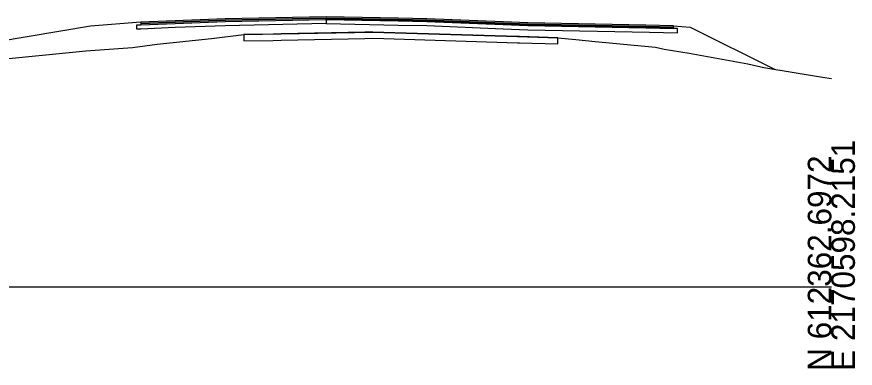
# Model space of a CAD drawing. Extents: x -26 to 1303, y -3010 to 12038.
# Drawn here: x 203.1 to 302.8, y 9990.3 to 10032.1 of the extents above; entities that cross this region are included whole.
import ezdxf

# ---------------------------------------------------------------- set-up
doc = ezdxf.new("R2010")
doc.units = 0
for name, color, linetype in [('RD_GPK_XS_Cell', 7, 'Continuous'), ('RD_XS_Base', 7, 'Continuous'), ('RD_XS_ExGround', 7, 'Continuous'), ('RD_XS_ExPaveRet', 7, 'Continuous'), ('RD_XS_Greenside', 7, 'Continuous'), ('RD_XS_Pave', 7, 'Continuous'), ('RD_XS_PaveOvlay_CP', 7, 'Continuous'), ('RD_XS_TieSlope', 7, 'Continuous')]:
    doc.layers.add(name, color=color, linetype=linetype)

msp = doc.modelspace()

# ---------------------------------------------------------------- linework, layer by layer
at = {"layer": 'RD_GPK_XS_Cell'}
msp.add_line((150, 10000), (300, 10000), dxfattribs=at)
at = {"layer": 'RD_XS_Base'}
for p, q in [((239.911, 10031.834), (239.911, 10031.944)), ((239.911, 10031.944), (239.911, 10031.49)), ((239.911, 10031.785), (239.911, 10031.834)), ((217.41, 10031.124), (217.621, 10031.133)), ((217.41, 10030.835), (217.41, 10031.124)), ((217.41, 10030.624), (217.41, 10030.835)), ((217.621, 10031.133), (217.91, 10031.144)), ((217.91, 10031.144), (221.985, 10031.307)), ((221.985, 10031.307), (227.911, 10031.544)), ((227.911, 10031.044), (221.985, 10030.807)), ((227.911, 10031.544), (239.911, 10031.785)), ((239.911, 10031.285), (227.911, 10031.044)), ((239.911, 10031.785), (239.911, 10031.785)), ((248.51, 10031.613), (239.911, 10031.785)), ((239.911, 10031.785), (239.911, 10031.785)), ((239.911, 10031.785), (239.911, 10031.44)), ((239.911, 10031.49), (239.911, 10031.285)), ((239.911, 10031.44), (239.911, 10031.285)), ((239.911, 10031.285), (248.51, 10031.113)), ((251.912, 10031.545), (248.51, 10031.613)), ((248.51, 10031.113), (251.912, 10031.045)), ((260.993, 10031.182), (251.912, 10031.545)), ((251.912, 10031.045), (260.993, 10030.682)), ((263.913, 10031.065), (260.993, 10031.182)), ((277.948, 10030.785), (263.913, 10031.065)), ((217.621, 10030.633), (217.41, 10030.624)), ((217.91, 10030.644), (217.621, 10030.633)), ((221.985, 10030.807), (217.91, 10030.644)), ((260.993, 10030.682), (263.913, 10030.565)), ((263.913, 10030.565), (278.379, 10030.277)), ((281.214, 10030.72), (277.948, 10030.785)), ((278.379, 10030.277), (281.714, 10030.21)), ((281.625, 10030.712), (281.214, 10030.72)), ((281.714, 10030.71), (281.625, 10030.712)), ((281.714, 10030.298), (281.714, 10030.71)), ((281.714, 10030.21), (281.714, 10030.298))]:
    msp.add_line(p, q, dxfattribs=at)
at = {"layer": 'RD_XS_ExGround'}
msp.add_lwpolyline([(200.182, 10026.931), (211.342, 10028.036), (216.898, 10028.458), (219.852, 10028.84), (226.304, 10029.519), (230.156, 10029.983), (234.593, 10030.057), (245.469, 10030.291), (262.662, 10029.762), (267.47, 10029.615), (269.627, 10029.394), (271.91, 10029.174), (279.071, 10028.498), (280.11, 10028.266), (283.1, 10027.773), (290.072, 10026.514), (291.971, 10026.075), (298.953, 10024.929), (300, 10024.765)], dxfattribs=at)
at = {"layer": 'RD_XS_ExPaveRet'}
for p, q in [((244.534, 10030.271), (234.593, 10030.057)), ((262.662, 10029.762), (246.785, 10030.251))]:
    msp.add_line(p, q, dxfattribs=at)
for points in [[(262.662, 10029.762), (246.785, 10030.251), (245.469, 10030.291), (244.534, 10030.271), (234.593, 10030.057), (233.642, 10030.041), (230.156, 10029.983), (230.156, 10029.86), (230.156, 10029.233), (233.642, 10029.291), (234.593, 10029.307), (244.534, 10029.521), (245.469, 10029.541), (246.785, 10029.501), (262.662, 10029.012), (262.915, 10029.004), (267.47, 10028.865), (267.47, 10029.606), (267.47, 10029.615), (262.915, 10029.754), (262.662, 10029.762)], [(234.593, 10030.057), (233.642, 10030.041), (230.156, 10029.983), (230.156, 10029.86), (230.156, 10029.233), (233.642, 10029.291), (234.593, 10029.307), (244.534, 10029.521), (245.469, 10029.541), (246.785, 10029.501), (262.662, 10029.012), (262.915, 10029.004), (267.47, 10028.865), (267.47, 10029.606), (267.47, 10029.615)], [(246.785, 10030.251), (245.469, 10030.291), (244.534, 10030.271)], [(267.47, 10029.615), (262.915, 10029.754), (262.662, 10029.762)]]:
    msp.add_lwpolyline(points, dxfattribs=at)
at = {"layer": 'RD_XS_Greenside'}
for p, q in [((211.91, 10030.982), (193.9, 10027.98)), ((283.214, 10030.878), (293.236, 10025.868))]:
    msp.add_line(p, q, dxfattribs=at)
at = {"layer": 'RD_XS_Pave'}
for p, q in [((227.911, 10031.862), (221.985, 10031.625)), ((239.911, 10032.103), (227.911, 10031.862)), ((239.911, 10031.944), (227.911, 10031.703)), ((227.911, 10031.703), (239.911, 10031.944)), ((248.51, 10031.931), (239.911, 10032.103)), ((239.911, 10031.834), (239.911, 10031.944)), ((239.911, 10031.944), (248.51, 10031.772)), ((248.51, 10031.772), (239.911, 10031.944)), ((239.911, 10031.944), (239.911, 10031.944)), ((239.911, 10031.944), (239.911, 10031.944)), ((239.911, 10031.944), (239.911, 10031.834)), ((239.911, 10031.785), (239.911, 10031.834)), ((239.911, 10031.834), (239.911, 10031.785)), ((251.912, 10031.863), (248.51, 10031.931)), ((260.993, 10031.5), (251.912, 10031.863)), ((221.985, 10031.625), (217.91, 10031.462)), ((221.985, 10031.466), (217.91, 10031.303)), ((217.91, 10031.303), (221.985, 10031.466)), ((217.91, 10031.462), (217.91, 10031.37)), ((217.91, 10031.37), (217.91, 10031.303)), ((217.91, 10031.144), (221.985, 10031.307)), ((217.91, 10031.303), (217.91, 10031.211)), ((217.91, 10031.211), (217.91, 10031.144)), ((227.911, 10031.703), (221.985, 10031.466)), ((221.985, 10031.466), (227.911, 10031.703)), ((221.985, 10031.307), (227.911, 10031.544)), ((227.911, 10031.544), (239.911, 10031.785)), ((239.911, 10031.785), (239.911, 10031.785)), ((239.911, 10031.785), (239.911, 10031.785)), ((239.911, 10031.785), (248.51, 10031.613)), ((248.51, 10031.772), (251.912, 10031.704)), ((251.912, 10031.704), (248.51, 10031.772)), ((248.51, 10031.613), (251.912, 10031.545)), ((251.912, 10031.704), (260.993, 10031.341)), ((260.993, 10031.341), (251.912, 10031.704)), ((251.912, 10031.545), (260.993, 10031.182)), ((263.913, 10031.383), (260.993, 10031.5)), ((260.993, 10031.341), (263.913, 10031.224)), ((263.913, 10031.224), (260.993, 10031.341)), ((260.993, 10031.182), (263.913, 10031.065)), ((277.948, 10031.103), (263.913, 10031.383)), ((263.913, 10031.224), (277.948, 10030.944)), ((277.948, 10030.944), (263.913, 10031.224)), ((263.913, 10031.065), (277.948, 10030.785)), ((281.214, 10031.038), (277.948, 10031.103)), ((277.948, 10030.944), (281.214, 10030.879)), ((281.214, 10030.879), (277.948, 10030.944)), ((281.214, 10030.907), (281.214, 10031.038)), ((281.214, 10030.879), (281.214, 10030.907)), ((281.214, 10030.748), (281.214, 10030.879)), ((277.948, 10030.785), (281.214, 10030.72)), ((281.214, 10030.72), (281.214, 10030.748))]:
    msp.add_line(p, q, dxfattribs=at)
at = {"layer": 'RD_XS_PaveOvlay_CP'}
for p, q in [((227.911, 10031.862), (221.985, 10031.625)), ((239.911, 10032.103), (227.911, 10031.862)), ((248.51, 10031.931), (239.911, 10032.103)), ((251.912, 10031.863), (248.51, 10031.931)), ((260.993, 10031.5), (251.912, 10031.863)), ((221.985, 10031.625), (217.91, 10031.462)), ((263.913, 10031.383), (260.993, 10031.5)), ((277.948, 10031.103), (263.913, 10031.383)), ((281.214, 10031.038), (277.948, 10031.103))]:
    msp.add_line(p, q, dxfattribs=at)
at = {"layer": 'RD_XS_TieSlope'}
for p, q in [((217.91, 10031.462), (211.91, 10030.982)), ((281.214, 10031.038), (283.214, 10030.878))]:
    msp.add_line(p, q, dxfattribs=at)

# ---------------------------------------------------------------- texts
at = {"layer": 'RD_GPK_XS_Cell'}
for s, p in [('E 2170598.2151', (302.8, 9990)), ('N 612362.6972', (300, 9990))]:
    msp.add_text(s, height=2.8, rotation=90, dxfattribs=at).set_placement(p)

doc.saveas('drawing.dxf')
